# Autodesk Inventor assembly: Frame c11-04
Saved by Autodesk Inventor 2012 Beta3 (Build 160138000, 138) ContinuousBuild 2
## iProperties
Created: 2011-01
Part Number: Frame c11-04
Document SubType Name: Assembly
Designer: Beta-8540w
_FrameDoc: Frame Assembly
_Version: 15.0.0
Author: Beta-8540w
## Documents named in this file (20)
- C:\Inventor 2012 Essentials\Assemblies\Chapter 11\Frame\Frame c11-04.iam
- C:\Inventor 2012 Essentials\Assemblies\Chapter 11\Frame\Skeleton-c11-04.ipt
- C:\Inventor 2012 Essentials\Assemblies\Chapter 11\Frame\ANSI 3x3x3_16 00000013.ipt
- ANSI 3x3x3_16 00000013.ipt
- C:\Inventor 2012 Essentials\Assemblies\Chapter 11\Frame\ANSI 3x3x3_16 00000014.ipt
- ANSI 3x3x3_16 00000014.ipt
- C:\Inventor 2012 Essentials\Assemblies\Chapter 11\Frame\ANSI 3x3x3_16 00000015.ipt
- ANSI 3x3x3_16 00000015.ipt
- C:\Inventor 2012 Essentials\Assemblies\Chapter 11\Frame\ANSI 3x3x3_16 00000016.ipt
- ANSI 3x3x3_16 00000016.ipt
- C:\Inventor 2012 Essentials\Assemblies\Chapter 11\Frame\ANSI 3x3x3_16 00000017.ipt
- ANSI 3x3x3_16 00000017.ipt
- C:\Inventor 2012 Essentials\Assemblies\Chapter 11\Frame\ANSI 3x3x3_16 00000018.ipt
- ANSI 3x3x3_16 00000018.ipt
- C:\Inventor 2012 Essentials\Assemblies\Chapter 11\Frame\ANSI L 1.5 x 1.5 x 3_16 00000019.ipt
- ANSI L 1.5 x 1.5 x 3_16 00000019.ipt
- C:\Inventor 2012 Essentials\Assemblies\Chapter 11\Frame\ANSI L 1.5 x 1.5 x 3_16 00000020.ipt
- ANSI L 1.5 x 1.5 x 3_16 00000020.ipt
- C:\Inventor 2012 Essentials\Assemblies\Chapter 11\Frame\ANSI 2 1_4x5_16 00000021.ipt
- ANSI 2 1_4x5_16 00000021.ipt
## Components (10 placed, 10 different names)
1. Frame Reference Model
2. ANSI 3x3x3_16 00000013:1
3. ANSI 3x3x3_16 00000014:1
4. ANSI 3x3x3_16 00000015:1
5. ANSI 3x3x3_16 00000016:1
6. ANSI 3x3x3_16 00000017:1
7. ANSI 3x3x3_16 00000018:1
8. ANSI L 1.5 x 1.5 x 3_16 00000019:1
9. ANSI L 1.5 x 1.5 x 3_16 00000020:1
10. ANSI 2 1_4x5_16 00000021:1
